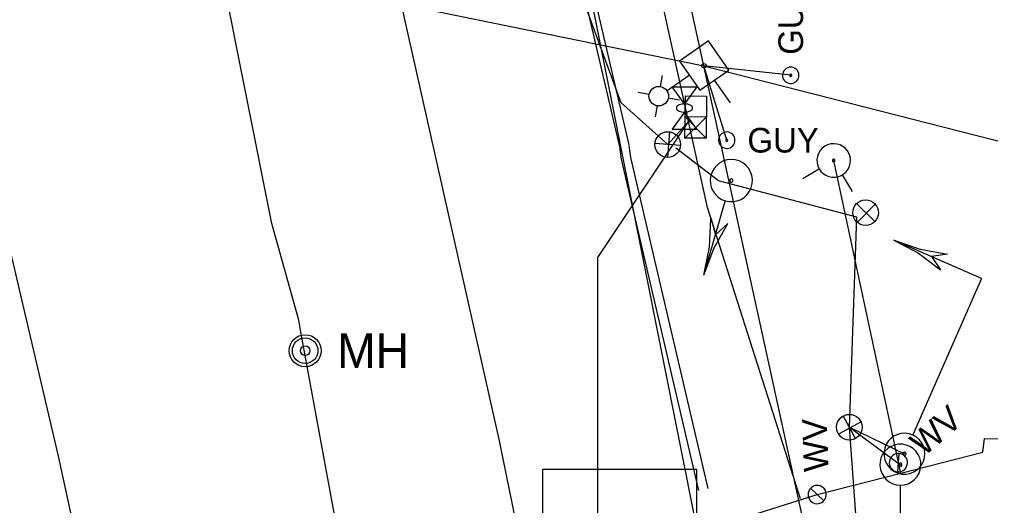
# Model space of a CAD drawing. Extents: x 596028 to 606371, y 330010 to 403088.
# Drawn here: x 604712 to 604863.7, y 339334.6 to 339410.5 of the extents above; entities that cross this region are included whole.
import ezdxf

# ---------------------------------------------------------------- set-up
doc = ezdxf.new("R2010")
doc.units = 0
for name, color, linetype in [('Default', 7, 'Continuous'), ('E_LTG', 7, 'Continuous'), ('E_SIG', 7, 'Continuous'), ('E_SIG_Conduit', 7, 'Continuous'), ('E_UTL_E', 7, 'Continuous'), ('E_UTL_E_Bold', 7, 'Continuous'), ('E_UTL_E_UG', 7, 'Continuous'), ('E_UTL_EGuyWire', 7, 'Continuous'), ('E_UTL_EPowerPole', 7, 'Continuous'), ('E_UTL_G_UG', 7, 'Continuous'), ('E_UTL_Overhead', 7, 'Continuous'), ('E_UTL_SAN_UG_MMSD', 7, 'Continuous'), ('E_UTL_T_UG', 7, 'Continuous'), ('E_UTL_W', 7, 'Continuous'), ('E_UTL_W_UG', 7, 'Continuous'), ('E_UTL_WHydrant', 7, 'Continuous')]:
    doc.layers.add(name, color=color, linetype=linetype)

# ---------------------------------------------------------------- blocks, each defined once
blk = doc.blocks.new('_U327')
at = {"layer": 'E_SIG'}
for p, q in [((0, 6.1), (0, -6.1)), ((-6.09, 0.4), (6.1, 0.4))]:
    blk.add_line(p, q, dxfattribs=at)
blk.add_circle((0, 0.01), 6.1, dxfattribs=at)
blk = doc.blocks.new('_U328')
at = {"layer": 'E_SIG'}
for p, q in [((0, 6.1), (0, -6.1)), ((-6.09, 0.4), (6.1, 0.4))]:
    blk.add_line(p, q, dxfattribs=at)
blk.add_circle((0, 0.01), 6.1, dxfattribs=at)
blk = doc.blocks.new('_U329')
at = {"layer": 'E_SIG'}
for p, q in [((0, 6.1), (0, -6.1)), ((-6.09, 0.4), (6.1, 0.4))]:
    blk.add_line(p, q, dxfattribs=at)
blk.add_circle((0, 0.01), 6.1, dxfattribs=at)
blk = doc.blocks.new('MH')
at = {"layer": 'Default'}
for radius in [15.24, 12.19, 4.57]:
    blk.add_circle((0, 0), radius, dxfattribs=at)
blk.add_text('MH', height=32.918, dxfattribs=at).set_placement((30.48, -16.46))
blk = doc.blocks.new('POINT_DISPLAY')
at = {"layer": 'Default'}
blk.add_line((0, 0), (0, 0), dxfattribs=at)
blk = doc.blocks.new('CBX')
at = {"layer": 'E_SIG'}
for p, q in [((0, 16.5), (-32.9, -16.5)), ((-32.9, 16.5), (0, -16.5)), ((0, -16.5), (0, 16.5))]:
    blk.add_line(p, q, dxfattribs=at)
blk.add_lwpolyline([(-32.9, -16.5), (-32.9, 16.5), (32.9, 16.5), (32.9, -16.5)], close=True, dxfattribs=at)
blk.add_blockref('POINT_DISPLAY', (0, 0), dxfattribs=at)
blk = doc.blocks.new('PPLM')
at = {"layer": 'E_LTG'}
for p, q in [((37.76, 4.8), (31.39, 11.15)), ((48.66, 4.8), (55.01, 11.15)), ((35.29, -0.66), (13.76, -0.66)), ((37.76, -6.1), (31.39, -12.47)), ((48.66, -6.1), (55.01, -12.47))]:
    blk.add_line(p, q, dxfattribs=at)
blk.add_circle((43.2, -0.66), 7.79, dxfattribs=at)
at = {"layer": 'E_UTL_EPowerPole'}
blk.add_line((-0.24, 14), (-0.24, 36.1), dxfattribs=at)
blk.add_lwpolyline([(-14.25, -14.05), (13.76, -14.05), (13.76, 14), (-14.25, 14)], close=True, dxfattribs=at)
blk.add_circle((0, 0), 1.81, dxfattribs=at)

msp = doc.modelspace()

# ---------------------------------------------------------------- linework, layer by layer
at = {"layer": 'E_SIG'}
msp.add_line((604821.23, 339385.29), (604814.55, 339390.36), dxfattribs=at)
for points in [[(604822.28, 339382.15), (604822.89, 339382.04), (604823.52, 339382.04), (604824.14, 339382.16), (604824.72, 339382.39), (604825.25, 339382.73), (604825.7, 339383.16), (604826.06, 339383.68), (604826.32, 339384.25), (604826.47, 339384.86), (604826.5, 339385.48), (604826.41, 339386.11), (604826.2, 339386.7), (604825.89, 339387.24), (604825.47, 339387.71), (604824.98, 339388.1), (604824.42, 339388.39), (604823.82, 339388.56), (604823.19, 339388.62), (604822.57, 339388.56), (604821.97, 339388.38), (604821.41, 339388.09), (604820.92, 339387.7), (604820.51, 339387.23), (604820.2, 339386.69), (604819.99, 339386.09), (604819.9, 339385.47), (604819.94, 339384.85), (604820.08, 339384.24), (604820.35, 339383.67), (604820.71, 339383.16), (604821.17, 339382.72), (604821.69, 339382.38), (604822.28, 339382.15)], [(604823.13, 339385.08), (604823.18, 339385.07), (604823.23, 339385.07), (604823.27, 339385.08), (604823.32, 339385.1), (604823.36, 339385.12), (604823.39, 339385.16), (604823.42, 339385.2), (604823.44, 339385.24), (604823.45, 339385.29), (604823.45, 339385.33), (604823.45, 339385.38), (604823.43, 339385.43), (604823.41, 339385.47), (604823.37, 339385.5), (604823.34, 339385.53), (604823.29, 339385.56), (604823.25, 339385.57), (604823.2, 339385.57), (604823.15, 339385.57), (604823.11, 339385.56), (604823.06, 339385.53), (604823.03, 339385.5), (604822.99, 339385.47), (604822.97, 339385.43), (604822.96, 339385.38), (604822.95, 339385.33), (604822.95, 339385.28), (604822.96, 339385.24), (604822.98, 339385.19), (604823.01, 339385.16), (604823.05, 339385.12), (604823.09, 339385.1), (604823.13, 339385.08)], [(604818.89, 339370.54), (604822.26, 339382.1)], [(604818.89, 339370.54), (604819.81, 339374.91), (604820.03, 339379.37)], [(604818.89, 339370.54), (604820.47, 339374.72), (604822.67, 339378.6)], [(604820.04, 339379.37), (604820.74, 339376.87)], [(604820.74, 339376.87), (604822.67, 339378.6)], [(604862.28, 339370.02), (604848.6, 339376.03)], [(604848.6, 339376.03), (604852.69, 339374.6), (604856.96, 339373.82)], [(604848.6, 339376.03), (604852.42, 339373.99), (604855.88, 339371.37)], [(604856.96, 339373.82), (604854.46, 339373.46)], [(604854.46, 339373.46), (604855.88, 339371.37)], [(604862.28, 339370.02), (604851.56, 339345.63)], [(604859.27, 339363.18), (604859.27, 339363.18)], [(604851.54, 339345.58), (604850.96, 339345.78), (604850.36, 339345.85), (604849.75, 339345.82), (604849.16, 339345.66), (604848.61, 339345.4), (604848.12, 339345.04), (604847.7, 339344.6), (604847.38, 339344.08), (604847.16, 339343.51), (604847.06, 339342.91), (604847.07, 339342.3), (604847.19, 339341.71), (604847.42, 339341.14), (604847.76, 339340.64), (604848.19, 339340.2), (604848.69, 339339.86), (604849.25, 339339.61), (604849.84, 339339.48), (604850.45, 339339.46), (604851.05, 339339.55), (604851.62, 339339.76), (604852.14, 339340.07), (604852.6, 339340.47), (604852.97, 339340.96), (604853.24, 339341.5), (604853.4, 339342.09), (604853.45, 339342.7), (604853.39, 339343.3), (604853.21, 339343.88), (604852.92, 339344.42), (604852.54, 339344.89), (604852.07, 339345.29), (604851.54, 339345.58)], [(604849.61, 339337.74), (604850.22, 339337.8), (604850.8, 339337.97), (604851.34, 339338.25), (604851.82, 339338.62), (604852.22, 339339.08), (604852.52, 339339.61), (604852.72, 339340.19), (604852.81, 339340.79), (604852.78, 339341.4), (604852.64, 339341.99), (604852.38, 339342.54), (604852.03, 339343.04), (604851.59, 339343.46), (604851.08, 339343.79), (604850.51, 339344.01), (604849.92, 339344.13), (604849.31, 339344.13), (604848.71, 339344.01), (604848.14, 339343.79), (604847.63, 339343.46), (604847.19, 339343.04), (604846.84, 339342.54), (604846.58, 339341.99), (604846.44, 339341.4), (604846.41, 339340.79), (604846.5, 339340.19), (604846.7, 339339.61), (604847, 339339.08), (604847.4, 339338.62), (604847.88, 339338.25), (604848.42, 339337.97), (604849, 339337.8), (604849.61, 339337.74)], [(604850.35, 339342.88), (604850.3, 339342.89), (604850.26, 339342.9), (604850.21, 339342.89), (604850.17, 339342.88), (604850.12, 339342.86), (604850.09, 339342.83), (604850.06, 339342.8), (604850.03, 339342.76), (604850.01, 339342.72), (604850.01, 339342.67), (604850.01, 339342.63), (604850.02, 339342.58), (604850.03, 339342.54), (604850.06, 339342.5), (604850.09, 339342.46), (604850.13, 339342.44), (604850.17, 339342.42), (604850.22, 339342.41), (604850.27, 339342.41), (604850.31, 339342.41), (604850.36, 339342.43), (604850.4, 339342.45), (604850.43, 339342.49), (604850.46, 339342.52), (604850.48, 339342.56), (604850.49, 339342.61), (604850.5, 339342.66), (604850.49, 339342.7), (604850.48, 339342.75), (604850.45, 339342.79), (604850.43, 339342.82), (604850.39, 339342.85), (604850.35, 339342.88)], [(604849.61, 339340.7), (604849.66, 339340.7), (604849.7, 339340.71), (604849.74, 339340.73), (604849.78, 339340.76), (604849.81, 339340.8), (604849.83, 339340.84), (604849.85, 339340.88), (604849.86, 339340.93), (604849.85, 339340.98), (604849.84, 339341.02), (604849.82, 339341.06), (604849.8, 339341.1), (604849.76, 339341.13), (604849.72, 339341.16), (604849.68, 339341.18), (604849.63, 339341.18), (604849.59, 339341.18), (604849.54, 339341.18), (604849.5, 339341.16), (604849.46, 339341.13), (604849.43, 339341.1), (604849.4, 339341.06), (604849.38, 339341.02), (604849.37, 339340.98), (604849.37, 339340.93), (604849.37, 339340.88), (604849.39, 339340.84), (604849.41, 339340.8), (604849.44, 339340.76), (604849.48, 339340.73), (604849.52, 339340.71), (604849.56, 339340.7), (604849.61, 339340.7)], [(604849.61, 339311.05), (604849.61, 339337.69)]]:
    msp.add_lwpolyline(points, dxfattribs=at)
at = {"layer": 'E_SIG_Conduit'}
for p, q in [((604842.8, 339379.58), (604821.23, 339385.29)), ((604841.64, 339346.8), (604842.8, 339379.58)), ((604844.47, 339308.35), (604841.64, 339346.8))]:
    msp.add_line(p, q, dxfattribs=at)
for points in [[(604799.17, 339415.97), (604805.96, 339397.51)], [(604813.27, 339390.95), (604805.96, 339397.51)], [(604841.64, 339346.8), (604850.25, 339342.65)], [(604841.64, 339346.8), (604849.61, 339340.94)]]:
    msp.add_lwpolyline(points, dxfattribs=at)
at = {"layer": 'E_UTL_E_Bold'}
for points in [[(604813.98, 339399.95), (604817.8, 339399.95)], [(604815.89, 339397.29), (604813.98, 339399.95)], [(604817.8, 339399.95), (604815.89, 339397.29)], [(604817.16, 339396.65), (604817.14, 339396.77), (604817.07, 339396.89), (604816.96, 339397), (604816.81, 339397.09), (604816.63, 339397.17), (604816.42, 339397.23), (604816.19, 339397.27), (604815.95, 339397.29), (604815.71, 339397.28), (604815.47, 339397.25), (604815.25, 339397.2), (604815.06, 339397.13), (604814.89, 339397.05), (604814.76, 339396.94), (604814.67, 339396.83), (604814.63, 339396.71), (604814.63, 339396.59), (604814.67, 339396.47), (604814.76, 339396.36), (604814.89, 339396.26), (604815.06, 339396.17), (604815.25, 339396.1), (604815.47, 339396.05), (604815.71, 339396.02), (604815.95, 339396.02), (604816.19, 339396.04), (604816.42, 339396.08), (604816.63, 339396.14), (604816.81, 339396.21), (604816.96, 339396.31), (604817.07, 339396.42), (604817.14, 339396.53), (604817.16, 339396.65)], [(604815.89, 339396.02), (604813.98, 339393.35)], [(604817.8, 339393.35), (604815.89, 339396.02)], [(604813.98, 339393.35), (604817.8, 339393.35)]]:
    msp.add_lwpolyline(points, dxfattribs=at)
at = {"layer": 'E_UTL_E_UG'}
msp.add_line((604813.27, 339390.95), (604816.55, 339394.62), dxfattribs=at)
msp.add_lwpolyline([(604784.34, 339222.62), (604775.95, 339262.38), (604768.41, 339297.38), (604762.12, 339328.3), (604755.94, 339361.93), (604755.64, 339363.5), (604751.45, 339378.59), (604743.59, 339418.09), (604735.46, 339449.75), (604728.77, 339482.52), (604722.85, 339509.42)], dxfattribs=at)
at = {"layer": 'E_UTL_EGuyWire'}
for p in [(604832.48, 339401.76), (604822.5, 339391.63)]:
    msp.add_line(p, (604818.92, 339403.26), dxfattribs=at)
for points in [[(604832.48, 339403.04), (604832.24, 339403.02), (604832.01, 339402.95), (604831.79, 339402.84), (604831.6, 339402.69), (604831.44, 339402.5), (604831.31, 339402.29), (604831.23, 339402.06), (604831.2, 339401.82), (604831.21, 339401.58), (604831.27, 339401.34), (604831.37, 339401.12), (604831.51, 339400.92), (604831.69, 339400.75), (604831.89, 339400.62), (604832.12, 339400.53), (604832.36, 339400.48), (604832.6, 339400.48), (604832.84, 339400.53), (604833.07, 339400.62), (604833.28, 339400.75), (604833.45, 339400.92), (604833.59, 339401.12), (604833.69, 339401.34), (604833.75, 339401.58), (604833.76, 339401.82), (604833.73, 339402.06), (604833.65, 339402.29), (604833.53, 339402.5), (604833.37, 339402.69), (604833.18, 339402.84), (604832.96, 339402.95), (604832.72, 339403.02), (604832.48, 339403.04)], [(604832.48, 339401.92), (604832.45, 339401.92), (604832.42, 339401.91), (604832.4, 339401.89), (604832.37, 339401.88), (604832.35, 339401.85), (604832.34, 339401.83), (604832.33, 339401.8), (604832.32, 339401.77), (604832.32, 339401.74), (604832.33, 339401.71), (604832.34, 339401.68), (604832.36, 339401.65), (604832.38, 339401.63), (604832.41, 339401.62), (604832.44, 339401.61), (604832.47, 339401.6), (604832.5, 339401.6), (604832.53, 339401.61), (604832.56, 339401.62), (604832.58, 339401.63), (604832.6, 339401.65), (604832.62, 339401.68), (604832.63, 339401.71), (604832.64, 339401.74), (604832.64, 339401.77), (604832.64, 339401.8), (604832.63, 339401.83), (604832.61, 339401.85), (604832.59, 339401.88), (604832.57, 339401.89), (604832.54, 339401.91), (604832.51, 339401.92), (604832.48, 339401.92)], [(604823.78, 339391.63), (604823.76, 339391.87), (604823.69, 339392.1), (604823.58, 339392.32), (604823.43, 339392.51), (604823.24, 339392.67), (604823.03, 339392.79), (604822.8, 339392.87), (604822.56, 339392.91), (604822.31, 339392.9), (604822.08, 339392.84), (604821.86, 339392.74), (604821.66, 339392.6), (604821.49, 339392.42), (604821.36, 339392.21), (604821.27, 339391.99), (604821.22, 339391.75), (604821.22, 339391.5), (604821.27, 339391.26), (604821.36, 339391.04), (604821.49, 339390.83), (604821.66, 339390.66), (604821.86, 339390.51), (604822.08, 339390.41), (604822.31, 339390.36), (604822.56, 339390.34), (604822.8, 339390.38), (604823.03, 339390.46), (604823.24, 339390.58), (604823.43, 339390.74), (604823.58, 339390.93), (604823.69, 339391.15), (604823.76, 339391.38), (604823.78, 339391.63)], [(604822.66, 339391.63), (604822.65, 339391.66), (604822.65, 339391.69), (604822.63, 339391.71), (604822.61, 339391.74), (604822.59, 339391.76), (604822.56, 339391.77), (604822.53, 339391.78), (604822.5, 339391.79), (604822.47, 339391.78), (604822.44, 339391.78), (604822.42, 339391.76), (604822.39, 339391.75), (604822.37, 339391.73), (604822.35, 339391.7), (604822.34, 339391.67), (604822.34, 339391.64), (604822.34, 339391.61), (604822.34, 339391.58), (604822.35, 339391.55), (604822.37, 339391.53), (604822.39, 339391.5), (604822.42, 339391.49), (604822.44, 339391.47), (604822.47, 339391.47), (604822.5, 339391.47), (604822.53, 339391.47), (604822.56, 339391.48), (604822.59, 339391.5), (604822.61, 339391.52), (604822.63, 339391.54), (604822.65, 339391.57), (604822.65, 339391.6), (604822.66, 339391.63)]]:
    msp.add_lwpolyline(points, dxfattribs=at)
at = {"layer": 'E_UTL_G_UG'}
for points in [[(604814.85, 339218.78), (604810.09, 339242.37), (604799.43, 339289.54), (604793.26, 339314.06), (604787.02, 339344.67), (604774.66, 339399.62), (604767.29, 339432.61), (604758.85, 339472.19), (604751.42, 339503.86)], [(604742.35, 339228.68), (604740.05, 339238.17), (604732.17, 339281.15), (604723.13, 339319.31), (604718.15, 339342.27), (604709.95, 339377.23), (604705.89, 339396.14), (604699.95, 339418.23), (604694.75, 339444.39), (604689.12, 339468.85), (604685.03, 339486.7), (604684.68, 339487.29), (604678.37, 339490.44), (604676.2, 339500.02)]]:
    msp.add_lwpolyline(points, dxfattribs=at)
at = {"layer": 'E_UTL_Overhead'}
for p, q in [((604818.92, 339403.26), (604792.43, 339523.66)), ((604841.61, 339299.51), (604818.92, 339403.26))]:
    msp.add_line(p, q, dxfattribs=at)
msp.add_lwpolyline([(604487.17, 339458.6), (604640.66, 339429.67), (604683.98, 339430.78), (604818.92, 339403.26), (604974.13, 339363.63), (605153.06, 339361.47)], dxfattribs=at)
at = {"layer": 'E_UTL_SAN_UG_MMSD'}
msp.add_line((604854.51, 339147.21), (604642.2, 340212.1), dxfattribs=at)
at = {"layer": 'E_UTL_T_UG'}
msp.add_lwpolyline([(604802.34, 339330.16), (604802.34, 339373.3), (604816.55, 339394.62)], dxfattribs=at)
msp.add_lwpolyline([(604793.79, 339340.25), (604817.79, 339340.25), (604817.79, 339319.89), (604793.79, 339319.89)], close=True, dxfattribs=at)
at = {"layer": 'E_UTL_W'}
for points in [[(604850.38, 339342.18), (604850.18, 339342.37), (604849.96, 339342.51), (604849.7, 339342.62), (604849.44, 339342.67), (604849.17, 339342.67), (604848.9, 339342.62), (604848.65, 339342.52), (604848.42, 339342.37), (604848.22, 339342.19), (604848.07, 339341.97), (604847.95, 339341.72), (604847.89, 339341.46), (604847.87, 339341.19), (604847.91, 339340.92), (604848, 339340.66), (604848.13, 339340.43), (604848.31, 339340.22), (604848.52, 339340.05), (604848.76, 339339.93), (604849.02, 339339.85), (604849.29, 339339.82), (604849.56, 339339.85), (604849.82, 339339.92), (604850.06, 339340.05), (604850.28, 339340.21), (604850.46, 339340.42), (604850.59, 339340.65), (604850.68, 339340.91), (604850.72, 339341.18), (604850.71, 339341.45), (604850.65, 339341.71), (604850.54, 339341.96), (604850.38, 339342.18)], [(604849.19, 339339.83), (604849.4, 339342.67)], [(604836.57, 339337.7), (604836.3, 339337.67), (604836.04, 339337.58), (604835.8, 339337.45), (604835.6, 339337.27), (604835.43, 339337.06), (604835.3, 339336.82), (604835.22, 339336.56), (604835.19, 339336.29), (604835.21, 339336.02), (604835.29, 339335.76), (604835.41, 339335.52), (604835.58, 339335.3), (604835.78, 339335.13), (604836.01, 339334.99), (604836.27, 339334.9), (604836.53, 339334.85), (604836.81, 339334.86), (604837.07, 339334.93), (604837.32, 339335.04), (604837.54, 339335.19), (604837.73, 339335.38), (604837.88, 339335.61), (604837.98, 339335.86), (604838.04, 339336.13), (604838.04, 339336.4), (604837.99, 339336.66), (604837.89, 339336.92), (604837.75, 339337.15), (604837.56, 339337.35), (604837.34, 339337.5), (604837.1, 339337.62), (604836.84, 339337.69), (604836.57, 339337.7)], [(604837.66, 339335.31), (604835.57, 339337.25)]]:
    msp.add_lwpolyline(points, dxfattribs=at)
at = {"layer": 'E_UTL_W_UG'}
msp.add_line((604849.7, 339339.62), (604839.19, 339388.45), dxfattribs=at)
for points in [[(604805.77, 339390.57), (604775.12, 339521.94), (604713.1, 339806.92)], [(604807.23, 339390.91), (604776.58, 339522.27), (604714.57, 339807.24)], [(604834.02, 339335.63), (604819.48, 339381.14), (604799.27, 339472.85)], [(604818.13, 339336.9), (604806.06, 339388.65), (604805.77, 339390.57)], [(604819.59, 339337.24), (604807.53, 339388.93), (604807.25, 339390.8)], [(604849.7, 339339.62), (604862.48, 339342.9), (604862.74, 339345.03), (605202.53, 339339.4)], [(604821.49, 339331.51), (604836.62, 339336.28), (604849.7, 339339.62)]]:
    msp.add_lwpolyline(points, dxfattribs=at)
at = {"layer": 'E_UTL_WHydrant'}
for points in [[(604836.65, 339389.1), (604836.57, 339388.61), (604836.59, 339388.11), (604836.7, 339387.63), (604836.91, 339387.17), (604837.19, 339386.76), (604837.55, 339386.41), (604837.96, 339386.14), (604838.42, 339385.95), (604838.91, 339385.85), (604839.41, 339385.84), (604839.9, 339385.93), (604840.37, 339386.11), (604840.79, 339386.37), (604841.15, 339386.71), (604841.45, 339387.11), (604841.66, 339387.57), (604841.78, 339388.05), (604841.81, 339388.55), (604841.75, 339389.04), (604841.59, 339389.51), (604841.35, 339389.95), (604841.03, 339390.33), (604840.64, 339390.64), (604840.2, 339390.88), (604839.72, 339391.02), (604839.23, 339391.08), (604838.73, 339391.04), (604838.25, 339390.9), (604837.8, 339390.68), (604837.41, 339390.37), (604837.08, 339390), (604836.82, 339389.57), (604836.65, 339389.1)], [(604839, 339388.5), (604838.99, 339388.47), (604838.99, 339388.43), (604839, 339388.39), (604839.02, 339388.36), (604839.04, 339388.32), (604839.07, 339388.3), (604839.1, 339388.28), (604839.13, 339388.26), (604839.17, 339388.25), (604839.21, 339388.25), (604839.25, 339388.26), (604839.28, 339388.27), (604839.32, 339388.29), (604839.34, 339388.32), (604839.37, 339388.35), (604839.38, 339388.39), (604839.39, 339388.42), (604839.39, 339388.46), (604839.39, 339388.5), (604839.38, 339388.54), (604839.36, 339388.57), (604839.33, 339388.6), (604839.3, 339388.62), (604839.27, 339388.64), (604839.23, 339388.65), (604839.2, 339388.65), (604839.16, 339388.65), (604839.12, 339388.64), (604839.09, 339388.62), (604839.06, 339388.6), (604839.03, 339388.57), (604839.01, 339388.54), (604839, 339388.5)], [(604836.96, 339387.13), (604834.35, 339385.59)], [(604840.52, 339386.22), (604842.06, 339383.62)]]:
    msp.add_lwpolyline(points, dxfattribs=at)

# ---------------------------------------------------------------- block references
at = {"layer": 'E_SIG_Conduit'}
for name, p, xscale, yscale, rotation in [('_U329', (604813.27, 339390.95), 0.3280833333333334, 0.32808333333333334, -94.48666147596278), ('_U328', (604844.17, 339380.31), 0.32808333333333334, 0.3280833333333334, -134.63665154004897), ('_U327', (604841.64, 339346.8), 0.32808333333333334, 0.3280833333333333, -151.60001930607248)]:
    msp.add_blockref(name, p, dxfattribs=dict(at, xscale=xscale, yscale=yscale, rotation=rotation))
at = {"layer": 'E_UTL_E', "xscale": 0.16404166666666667, "yscale": 0.16404166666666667}
msp.add_blockref('MH', (604756.65, 339358.75), dxfattribs=at)
at = {"layer": 'E_UTL_E_UG', "xscale": 0.1, "yscale": 0.10000000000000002, "rotation": 89.38631717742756}
msp.add_blockref('CBX', (604817.65, 339395.24), dxfattribs=at)
at = {"layer": 'E_UTL_EPowerPole', "xscale": 0.19684999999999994, "yscale": 0.19684999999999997, "rotation": -145.20219693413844}
msp.add_blockref('PPLM', (604818.94, 339403.25), dxfattribs=at)

# ---------------------------------------------------------------- texts
at = {"layer": 'E_UTL_EGuyWire'}
msp.add_text('GUY', height=3.85, rotation=90, dxfattribs=at).set_placement((604834.41, 339404.97))
msp.add_text('GUY', height=3.85, dxfattribs=at).set_placement((604825.71, 339389.7))
at = {"layer": 'E_UTL_W'}
for rotation, p in [(40.6918, (604853.26, 339342.11)), (92.1084, (604838.41, 339339.91))]:
    msp.add_text('WV', height=3.85, rotation=rotation, dxfattribs=at).set_placement(p)

doc.saveas('drawing.dxf')
